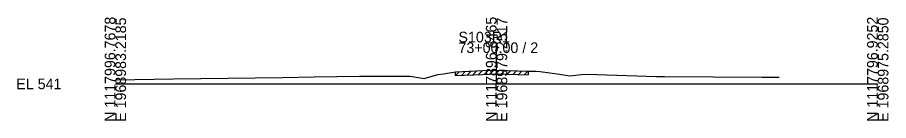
# Model space of a CAD drawing. Extents: x -26 to 203, y -10 to 12018.
# Drawn here: x -25.7 to 202.8, y 10490.3 to 10517.5 of the extents above; entities that cross this region are included whole.
import ezdxf

# ---------------------------------------------------------------- set-up
doc = ezdxf.new("R2010")
doc.units = 0
for name, color, linetype in [('Level 60', 7, 'Continuous'), ('Level 61', 7, 'Continuous'), ('Level 63', 7, 'Continuous')]:
    doc.layers.add(name, color=color, linetype=linetype)

msp = doc.modelspace()

# ---------------------------------------------------------------- linework, layer by layer
at = {"layer": 'Level 60'}
for p, q in [((89.26, 10503.19), (96.42, 10503.49)), ((96.42, 10503.49), (100.06, 10503.64)), ((100.06, 10503.64), (102.83, 10503.55)), ((102.83, 10503.55), (108.27, 10503.39)), ((108.27, 10503.39), (110.33, 10503.32)), ((0, 10501.07), (15.29, 10501.31)), ((15.29, 10501.31), (43.84, 10501.68)), ((43.84, 10501.68), (52.19, 10501.85)), ((52.19, 10501.85), (64.07, 10502)), ((64.07, 10502), (76.87, 10502.06)), ((76.87, 10502.06), (77.32, 10501.99)), ((77.32, 10501.99), (81.01, 10501.38)), ((81.01, 10501.38), (83.14, 10502.03)), ((83.14, 10502.03), (84.57, 10502.45)), ((84.57, 10502.45), (86.11, 10502.69)), ((86.11, 10502.69), (89.26, 10503.19)), ((110.33, 10503.32), (111.43, 10503.27)), ((111.43, 10503.27), (116.53, 10502.53)), ((116.53, 10502.53), (119.25, 10502.13)), ((119.25, 10502.13), (122.29, 10502.44)), ((122.29, 10502.44), (123.8, 10502.6)), ((123.8, 10502.6), (141.99, 10501.98)), ((141.99, 10501.98), (144.04, 10501.92)), ((144.04, 10501.92), (169.6, 10501.8)), ((169.6, 10501.8), (174.17, 10501.73))]:
    msp.add_line(p, q, dxfattribs=at)
at = {"layer": 'Level 61'}
for p, q in [((92.26, 10502.32), (93.3, 10503.36)), ((93.76, 10502.38), (94.8, 10503.43)), ((95.26, 10502.45), (96.3, 10503.49)), ((96.76, 10502.51), (97.8, 10503.55)), ((98.26, 10502.57), (99.3, 10503.61)), ((99.76, 10502.63), (100.75, 10503.62)), ((101.26, 10502.61), (102.23, 10503.57)), ((102.76, 10502.56), (103.73, 10503.53)), ((104.26, 10502.51), (105.23, 10503.48)), ((105.76, 10502.46), (106.73, 10503.43)), ((107.26, 10502.42), (108.23, 10503.39)), ((108.27, 10503.39), (108.27, 10502.39)), ((89.26, 10502.19), (90.3, 10503.23)), ((89.26, 10502.19), (89.26, 10503.19)), ((89.26, 10502.19), (96.42, 10502.49)), ((90.76, 10502.25), (91.8, 10503.3)), ((96.42, 10502.49), (100.06, 10502.64)), ((100.06, 10502.64), (102.83, 10502.55)), ((102.83, 10502.55), (108.27, 10502.39))]:
    msp.add_line(p, q, dxfattribs=at)
at = {"layer": 'Level 63'}
for p, q in [((100, 10500), (100, 10510.93)), ((0, 10500), (100, 10500)), ((100, 10500), (200, 10500))]:
    msp.add_line(p, q, dxfattribs=at)

# ---------------------------------------------------------------- texts
for s, p in [('N 1117996.7678', (0, 10490)), ('E 1968983.2185', (2.8, 10490)), ('N 1117896.8465', (100, 10490)), ('E 1968979.2517', (102.8, 10490)), ('N 1117796.9252', (200, 10490)), ('E 1968975.2850', (202.8, 10490))]:
    msp.add_text(s, height=2.8, rotation=90, dxfattribs=at).set_placement(p)
for s, p in [('S103R1', (90, 10510.93)), ('73+00.00 / 2', (90, 10508.13)), ('EL 541', (-26, 10498.6))]:
    msp.add_text(s, height=2.8, dxfattribs=at).set_placement(p)

doc.saveas('drawing.dxf')
